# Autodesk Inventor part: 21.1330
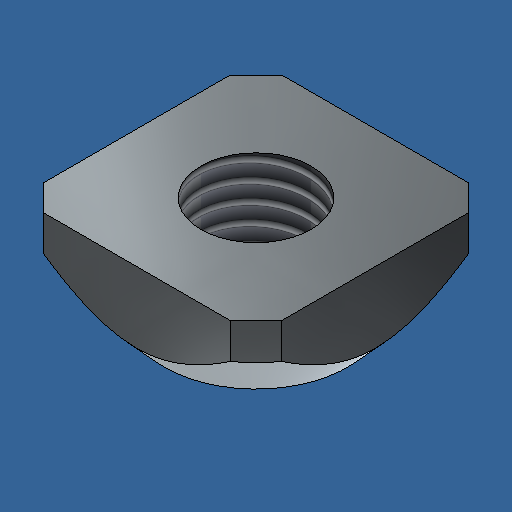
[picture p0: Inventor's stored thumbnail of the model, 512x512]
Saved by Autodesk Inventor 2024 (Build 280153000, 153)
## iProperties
Created: 2006-12
Part Number: 21.1330
Document SubType Name: Modeling
Designer: Andy Moles
Material: Steel, Mild
Mass: 4.93583 g
Surface Area: 5.644 cm^2
Volume: 0.628768 cm^3
Density: 7.85 g/cm^3
Description: M6 SQUARE NUT
Vendor: S
Appearance: Zinc
Title: M6 SQUARE NUT
Author: Andy Moles
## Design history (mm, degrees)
sketch "Sketch2"
  geometry: L1 (-5.086, -6.5)-(5.086, -6.5); L2 (6.5, -5.086)-(6.5, 5.086); L3 (5.086, 6.5)-(-5.086, 6.5); L4 (-6.5, 5.086)-(-6.5, -5.086); L5 (-6.5, 6.5)-(6.5, -6.5); L6 (5.086, 6.5)-(6.5, 5.086); L7 (0, -6.5)-(0, 6.5); L8 (-6.5, 0)-(6.5, 0); L9 (-5.086, 6.5)-(-6.5, 5.086); L10 (-5.086, -6.5)-(-6.5, -5.086); L11 (5.086, -6.5)-(6.5, -5.086); C1 r 3 at (0, 0); 2 further points
  constraints: 22 end point, 6 symmetric about line, 4 parallel, 3 midpoint, 2 coincident, 2 perpendicular, 1 centre point, 1 horizontal
  dimensions: "THREAD" = 6 diameter of C1; "d3" = 45 deg angle of L3 L6 (derived); "d4" = 2 distance of L3.start L2.end
extrude "Extrusion1" new body sketch "Sketch2" distance "d5" = 5.5; taper "d6" = 0 deg
workplane "Work Plane1"
sketch "Sketch4"
  geometry: L1 (11.192, 0)-(5.192, 0) reference; L2 (8.192, 0)-(13.192, 0); L3 (16.385, 5.5)-(16.385, 3.5); L4 (13.192, 0)-(16.797, 3.952); L5 (13.192, 0)-(16.385, 0); L6 (16.385, 3.5)-(16.385, 0); L7 (16.797, 3.952)-(16.797, -0.412); L8 (16.797, -0.412)-(13.192, -0.412); L9 (13.192, -0.412)-(13.192, 0); L10 (8.192, 5.5)-(8.192, 0); L11 (16.385, 5.5)-(16.385, 0) reference; L12 (16.385, 3.5)-(17.502, 3.5); L13 (9.192, 5.5)-(16.385, 5.5) reference
  constraints: 20 end point, 6 perpendicular, 1 collinear, 1 midpoint, 1 parallel, 1 point on line
  dimensions: "d10" = 5 distance of L2.start L2.end; "d15" = 2 distance between parallel lines of L12 L13
revolve "Revolution1" sketch "Sketch4" stored, may be unused: angle "d12" = 90 deg
thread "Thread1" dims "d13" = 10, "d14" = 0
body "Solid1"
